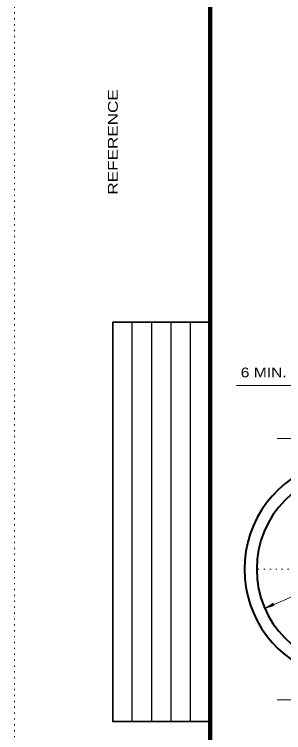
# Model space of a CAD drawing. Extents: x 312583 to 312854, y 144419 to 144597.
# Drawn here: x 312601.2 to 312622.2, y 144489.8 to 144545.9 of the extents above; entities that cross this region are included whole.
import ezdxf

# ---------------------------------------------------------------- set-up
doc = ezdxf.new("R2010")
doc.units = 0
doc.header["$LTSCALE"] = 0.3
doc.linetypes.add('DOTTED', pattern=[1.5, 0.3, -1.2])
doc.layers.add('1', color=7, linetype='Continuous', lineweight=40)
doc.layers.add('62', color=7, linetype='DOTTED', lineweight=13)

msp = doc.modelspace()

# ---------------------------------------------------------------- linework, layer by layer
at = {"layer": '1', "lineweight": 25}
for p, q in [((312610.4087, 144490.6573), (312610.4087, 144521.8756)), ((312611.9315, 144490.6573), (312611.9315, 144521.8756)), ((312613.4543, 144490.6573), (312613.4543, 144521.8756)), ((312614.9772, 144490.6573), (312614.9772, 144521.8756))]:
    msp.add_line(p, q, dxfattribs=at)
at = {"layer": '1', "lineweight": 13}
for p, q in [((312623.0587, 144516.9233), (312618.5544, 144516.9233)), ((312627.6663, 144512.791), (312621.74, 144512.791)), ((312627.8043, 144502.5713), (312620.774, 144499.5046)), ((312620.774, 144499.5046), (312621.441, 144499.9033)), ((312621.441, 144499.9033), (312621.257, 144499.7116)), ((312620.774, 144499.5046), (312621.5177, 144499.727)), ((312621.5177, 144499.727), (312621.257, 144499.7116)), ((312627.6663, 144492.344), (312621.74, 144492.344))]:
    msp.add_line(p, q, dxfattribs=at)
at = {"layer": '1', "linetype": 'DOTTED', "lineweight": 13}
msp.add_line((312626.7847, 144502.5713), (312619.969, 144502.5713), dxfattribs=at)
at = {"layer": '1', "lineweight": 158}
msp.add_lwpolyline([(312616.5, 144423.1446), (312616.5, 144585.0846), (312849, 144585.0846)], dxfattribs=at)
at = {"layer": '1', "lineweight": 35}
msp.add_lwpolyline([(312616.5, 144490.6573), (312608.8858, 144490.6573), (312608.8858, 144521.8756), (312616.5, 144521.8756)], dxfattribs=at)
at = {"layer": '1'}
for radius, start, end in [(8.625, 106.01339, 180), (7.6667, 91.18394, 180), (8.625, 180, 253.98661), (7.6667, 180, 268.81606)]:
    msp.add_arc((312627.8043, 144502.5687), radius, start, end, dxfattribs=at)
at = {"layer": '62'}
msp.add_line((312601.2, 144418.5846), (312601.2, 144596.7846), dxfattribs=at)

# ---------------------------------------------------------------- texts
at = {"layer": '1', "width": 1.3}
msp.add_text('REFERENCE                                                              ', height=0.7682, rotation=90, dxfattribs=at).set_placement((312609.2854, 144531.8549))
at = {"layer": '1', "width": 1.2}
msp.add_text('6 MIN.', height=0.76, dxfattribs=at).set_placement((312618.8942, 144517.5689))

doc.saveas('drawing.dxf')
